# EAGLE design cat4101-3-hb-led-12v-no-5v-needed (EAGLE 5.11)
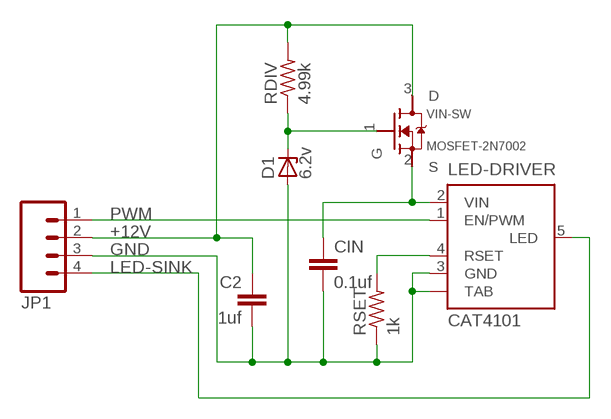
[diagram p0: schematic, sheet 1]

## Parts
C2  1uf  C-EUC1206  [C1206]
CIN  0.1uf  C-EUC1206  [C1206]
D1  6.2v  DIODE-ZENER-SMD-6.2V  [SOD-323]
JP1  M04PTH  [1X04]
LED-DRIVER  CAT4101  [TO263_5]
RDIV  4.99k  R-US_R1206  [R1206]
RSET  1k  R-US_R1210  [R1210]
VIN-SW  MOSFET-2N7002  [SOT23-3]

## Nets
+12V: C2.1 JP1.2 RDIV.2 VIN-SW.3(D)
GND: C2.2 CIN.2 D1.2(A) JP1.3 LED-DRIVER.3(GND) LED-DRIVER.TAB RSET.1
LED-SINK: JP1.4 LED-DRIVER.5(LED)
N$1: D1.1(C) RDIV.1 VIN-SW.1(G)
N$2: CIN.1 LED-DRIVER.2(VIN) VIN-SW.2(S)
N$7: LED-DRIVER.4(RSET) RSET.2
PWM: JP1.1 LED-DRIVER.1(EN/PWM)

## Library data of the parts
C2 CIN = rcl:C-EU: CAPACITOR, European symbol
D1 = trl:DIODE-ZENER-SMD-6.2V
JP1 = SparkFun:M04: Header 4 Standard 4-pin 0.1" header. Use with straight break away headers (SKU : PRT-00116), right angle break away headers (PRT-00553), swiss pins (PRT-00743), machine pins (PRT-00117), and female headers (PRT-00115). Molex polarized connector foot print use with SKU : PRT-08231 with associated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
LED-DRIVER = on-semiconductor:CAT4101: 1A Constant-Current LED Driver with PWM Dimming Source: ON Semiconductor .. 4101.pdf; MPN: CAT4101TV-T75; OC_FARNELL: 1718452; OC_NEWARK: 08R5264
RDIV RSET = resistor:R-US_: RESISTOR, American symbol
VIN-SW = trl:MOSFET-2N7002

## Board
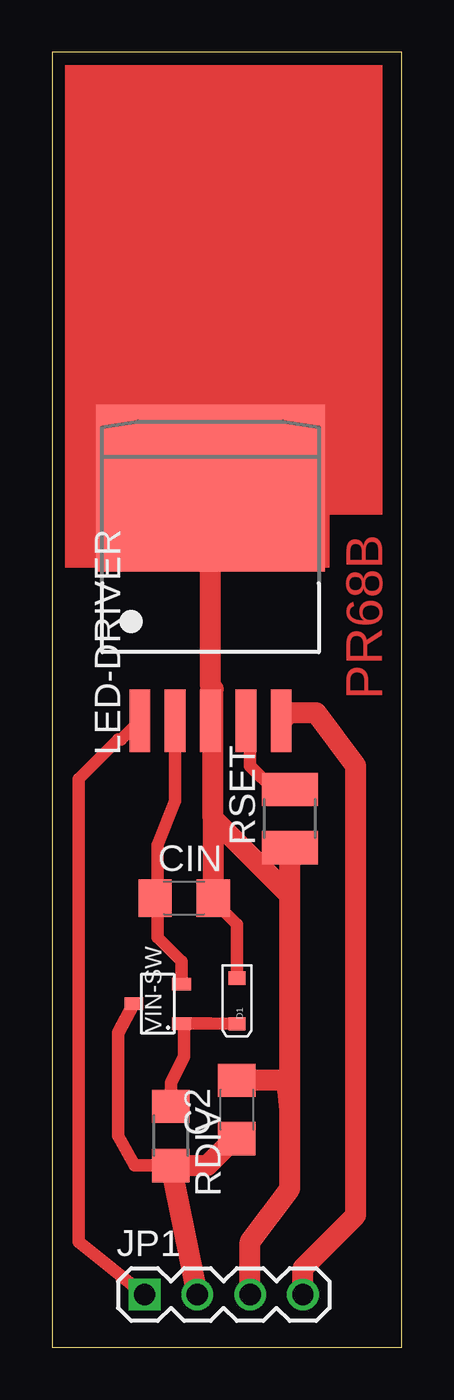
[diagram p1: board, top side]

Size 16.82 x 62.22 mm. Coordinates in mm from the lower left corner, seen from the top.
Outline: 0,0 16.82,0 16.82,62.22 0,62.22 0,0
Copper layers (1*16): Top 0.035mm / dielectric 1.5mm / Bottom 0.035mm
Design rules "default": minimum track width 10mil, minimum drill 24mil, track to track 8mil, track to pad 8mil, pad to pad 8mil, via to via 8mil, smd to smd 8mil, copper to edge 40mil, drill to drill 8mil, minimum pad ring 10mil, minimum via ring 8mil, stop-mask expansion 4mil, vias tented up to drill 0mil, thermal gap 10mil

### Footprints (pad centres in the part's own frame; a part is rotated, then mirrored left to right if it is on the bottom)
C1206 = smd 1.6 x 1.8: 1 -1.4,0; 2 1.4,0
SOD-323 = smd 0.63 x 0.83: 1 -0.96,0; 2 1.23,0
1X04 = drill 1.016 square: 1 0,0 | drill 1.016 round: 2 2.54,0; 3 5.08,0; 4 7.62,0
TO263_5 = smd 1 x 3: 1 -3.4,-8; 2 -1.7,-8; 3 0,-8; 4 1.7,-8; 5 3.4,-8 | smd 11 x 8: TAB 0,3.175
R1206 = smd 1.6 x 1.803: 1 -1.422,0; 2 1.422,0
R1210 = smd 1.6 x 2.7: 1 -1.4,0; 2 1.4,0
SOT23-3 = smd 0.6 x 0.9: 1 -0.95,-1.15; 2 0.95,-1.15; 3 0,1.15

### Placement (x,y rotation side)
C2  8.89,11.43 90 top
CIN  6.35,21.59 0 top
D1  8.89,16.51 90 top
JP1  4.45,2.54 0 top
LED-DRIVER  7.62,38.1 0 top
RDIV  5.71,10.16 270 top
RSET  11.43,25.4 90 top
VIN-SW  5.08,16.51 90 top

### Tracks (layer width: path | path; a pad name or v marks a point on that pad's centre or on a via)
+12V
  Top 0.61: RDIV.2 3.96,8.74 3.17,10.16 3.17,15.12 VIN-SW.3
  Top 1.016: JP1.2 RDIV.2 7.47,8.74 8.89,10.16 C2.1
GND
  Top 0.61: 7.75,21.46 8.89,20.32 D1.2
  Top 1.016: 7.62,31.75 LED-DRIVER.3 | 7.62,31.75 LED-DRIVER.TAB | 7.75,25.4 CIN.2 7.75,21.46 | 7.75,25.4 7.75,31.62 7.62,31.75 | JP1.3 9.53,5.08 11.43,7.62 11.43,11.43 | 11.43,11.43 11.43,21.72 | 11.43,21.72 7.75,25.4 | 11.43,21.72 RSET.1 | C2.2 11.3,12.83 11.43,11.43
LED-SINK
  Top 1.016: JP1.4 12.06,3.81 14.61,6.35 14.61,27.94 12.7,30.48 11.4,30.48 LED-DRIVER.5
N$1
  Top 0.61: D1.1 7.63,15.56 VIN-SW.1 6.35,15.44 6.35,13.97 5.71,12.7 RDIV.1
N$2
  Top 0.61: VIN-SW.2 6.23,18.54 5.08,19.68 5.08,21.46 | LED-DRIVER.2 5.92,26.24 5.08,24.13 5.08,21.72
  Top 1.016: 5.08,21.46 CIN.1 5.08,21.72
N$7
  Top 0.61: RSET.2 10.66,26.8 9.53,27.94 9.53,29.89 LED-DRIVER.4
PWM
  Top 0.61: JP1.1 1.27,5.08 1.27,27.3 3.17,29.21 3.33,29.21 LED-DRIVER.1
(copper drawn outside any net)
  shapes: Top area x2

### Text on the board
Top: PR68B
